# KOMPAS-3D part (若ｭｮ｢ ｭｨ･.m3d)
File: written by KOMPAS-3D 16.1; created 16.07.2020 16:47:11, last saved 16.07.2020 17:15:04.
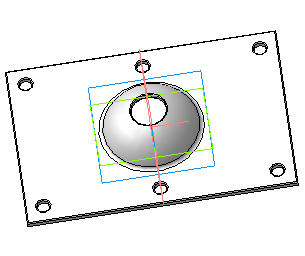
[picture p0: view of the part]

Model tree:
1. Эскиз:1
2. Операция вращения:1
     Толщина стенки 1 = 3; Угол 1 = 360
3. Эскиз:2
4. Вырезать элемент выдавливания:1
     Расстояние 2 = 30; Расстояние 1 = 30
5. Эскиз:3
6. Операция выдавливания:1
     Расстояние 1 = 3
7. Скругление:1
     Радиус = 2
8. Фаска:1
     Угол = 45; Длина 1 = 0.5; Длина 2 = 0.5
9. Эскиз:4
10. Вырезать элемент выдавливания:2
     Расстояние 2 = 30; Расстояние 1 = 30
11. Фаска:2
     Угол = 45; Длина 1 = 0.5; Длина 2 = 0.5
